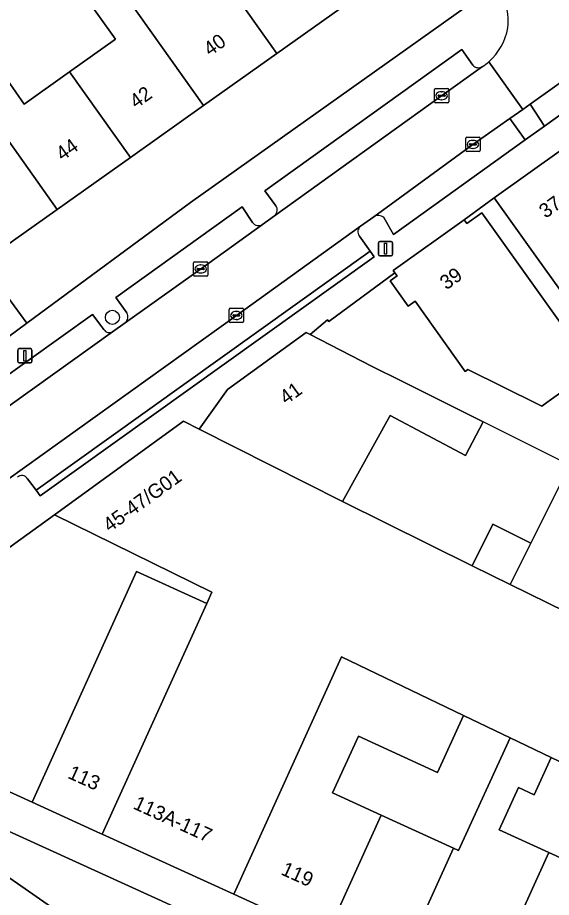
# Model space of a CAD drawing. Extents: x 161881 to 162523, y 381678 to 382381.
# Drawn here: x 162188.6 to 162225.8, y 381835.8 to 381897.2 of the extents above; entities that cross this region are included whole.
import ezdxf

# ---------------------------------------------------------------- set-up
doc = ezdxf.new("R2010")
doc.units = 0
for name, color, linetype in [('IMGEO_Boom', 7, 'Continuous'), ('IMGEO_Erf', 7, 'Continuous'), ('IMGEO_Fietspad_open', 7, 'Continuous'), ('IMGEO_Groenvoorziening', 7, 'Continuous'), ('IMGEO_Kolk', 7, 'Continuous'), ('IMGEO_Lichtmast', 7, 'Continuous'), ('IMGEO_Muur', 7, 'Continuous'), ('IMGEO_Pand', 7, 'Continuous'), ('IMGEO_Pand_nummerreeks', 7, 'Continuous'), ('IMGEO_Parkeervlak_open', 7, 'Continuous'), ('IMGEO_Rijbaan_lokaal_gesloten', 7, 'Continuous'), ('IMGEO_Rijbaan_lokaal_open', 7, 'Continuous'), ('IMGEO_Voetpad_open', 7, 'Continuous')]:
    doc.layers.add(name, color=color, linetype=linetype)

msp = doc.modelspace()

# ---------------------------------------------------------------- linework, layer by layer
at = {"layer": 'IMGEO_Boom'}
msp.add_circle((162195.219, 381876.245), 0.489, dxfattribs=at)
at = {"layer": 'IMGEO_Erf'}
for points in [[(162192.985, 381899.113), (162194.885, 381900.463), (162197.327, 381902.197), (162199.786, 381898.734), (162202.449, 381900.625), (162205.043, 381902.467), (162199.857, 381909.77), (162197.982, 381912.41), (162174.798, 381896.036), (162181.899, 381886.04), (162184.511, 381887.894), (162183.222, 381889.708), (162183.269, 381891.068), (162182.383, 381892.316), (162180.235, 381895.341), (162182.182, 381896.724), (162184.329, 381893.698), (162186.276, 381895.081), (162187.902, 381892.79), (162189.079, 381891.131), (162192.238, 381893.374), (162195.444, 381895.65)], [(162219.928, 381897.942), (162217.025, 381901.99), (162216.426, 381901.565), (162216.676, 381900.636), (162214.964, 381899.393), (162214.161, 381899.956), (162211.795, 381898.276), (162206.689, 381894.65), (162201.583, 381891.024), (162196.478, 381887.399), (162191.372, 381883.773), (162186.145, 381880.061), (162189.26, 381875.839), (162200.679, 381884.262)], [(162217.888, 381844.488), (162212.383, 381847.004), (162210.577, 381843.05), (162213.957, 381841.506), (162219.021, 381839.193), (162219.368, 381839.034), (162222.963, 381846.903), (162219.706, 381848.467)], [(162237.733, 381842.257), (162241.739, 381840.426), (162242.567, 381842.238), (162238.73, 381843.992), (162238.196, 381842.822), (162232.406, 381845.468), (162230.931, 381843.076), (162225.821, 381845.53), (162224.634, 381842.932), (162223.557, 381843.424), (162222.21, 381840.476), (162225.66, 381838.899), (162230.754, 381836.572), (162229.277, 381833.339), (162225.862, 381825.851), (162227.18, 381825.249), (162228.266, 381824.753), (162228.546, 381824.625), (162231.967, 381832.11), (162233.525, 381835.519), (162234.459, 381835.092)]]:
    msp.add_lwpolyline(points, close=True, dxfattribs=at)
msp.add_lwpolyline([(162227.003, 381877.365), (162224.754, 381880.517), (162221.85, 381884.587), (162219.757, 381883.039), (162219.932, 381882.795), (162220.983, 381883.545), (162228.778, 381872.621), (162225.523, 381870.299), (162225.177, 381870.052), (162225.045, 381870.118), (162224.95, 381870.164), (162220.024, 381872.598), (162219.836, 381872.464), (162216.329, 381877.377), (162215.841, 381877.029), (162214.585, 381878.789), (162215.074, 381879.138), (162214.928, 381879.343), (162210.308, 381875.962), (162210.218, 381876.081), (162209.012, 381875.04), (162213.292, 381872.838), (162215.453, 381871.759), (162221.091, 381868.944), (162219.842, 381866.613), (162214.594, 381869.388), (162211.275, 381863.392), (162220.321, 381858.911), (162221.768, 381861.808), (162224.418, 381860.495), (162227.131, 381865.927)], dxfattribs=at)
at = {"layer": 'IMGEO_Fietspad_open'}
for points in [[(162297.281, 381790.934), (162283.991, 381796.906), (162276.913, 381800.086), (162237.824, 381817.651), (162177.947, 381844.935)], [(162183.799, 381840.053), (162184.069, 381839.866), (162192.812, 381833.805), (162194.089, 381833.367), (162198.754, 381831.251), (162197.694, 381828.855), (162197.222, 381827.799), (162199.963, 381826.58), (162201.558, 381830.008), (162248.9, 381808.653), (162250.093, 381808.023), (162257.97, 381806.387), (162264.876, 381803.292), (162275.916, 381798.35), (162283.117, 381795.079), (162296.058, 381789.157)]]:
    msp.add_lwpolyline(points, dxfattribs=at)
at = {"layer": 'IMGEO_Groenvoorziening'}
msp.add_lwpolyline([(162225.354, 381889.595), (162224.359, 381891.116), (162223.84, 381890.752), (162222.952, 381890.129), (162224.004, 381888.624)], close=True, dxfattribs=at)
at = {"layer": 'IMGEO_Kolk'}
for p, q in [((162217.682, 381891.288), (162217.682, 381892.14)), ((162217.757, 381892.214), (162218.609, 381892.214)), ((162218.17, 381891.994), (162218.195, 381891.994)), ((162218.683, 381892.14), (162218.683, 381891.288)), ((162217.941, 381891.708), (162217.941, 381891.72)), ((162218.379, 381891.671), (162217.981, 381891.671)), ((162217.984, 381891.757), (162218.382, 381891.757)), ((162218.193, 381891.434), (162218.168, 381891.434)), ((162218.425, 381891.72), (162218.425, 381891.708)), ((162218.609, 381891.214), (162217.757, 381891.214)), ((162219.943, 381888.815), (162220.795, 381888.815)), ((162219.868, 381887.889), (162219.868, 381888.741)), ((162220.127, 381888.309), (162220.127, 381888.321)), ((162220.565, 381888.272), (162220.167, 381888.272)), ((162220.17, 381888.358), (162220.568, 381888.358)), ((162220.356, 381888.595), (162220.381, 381888.595)), ((162220.611, 381888.321), (162220.611, 381888.309)), ((162220.869, 381888.741), (162220.869, 381887.889)), ((162220.795, 381887.815), (162219.943, 381887.815)), ((162220.379, 381888.035), (162220.354, 381888.035)), ((162200.88, 381879.193), (162200.88, 381880.045)), ((162200.955, 381880.119), (162201.807, 381880.119)), ((162201.139, 381879.613), (162201.139, 381879.625)), ((162201.577, 381879.576), (162201.179, 381879.576)), ((162201.182, 381879.662), (162201.58, 381879.662)), ((162201.368, 381879.899), (162201.393, 381879.899)), ((162201.623, 381879.625), (162201.623, 381879.613)), ((162201.881, 381880.045), (162201.881, 381879.193)), ((162201.807, 381879.119), (162200.955, 381879.119)), ((162201.391, 381879.339), (162201.366, 381879.339)), ((162203.369, 381875.95), (162203.369, 381876.802)), ((162203.444, 381876.876), (162204.296, 381876.876)), ((162203.857, 381876.656), (162203.882, 381876.656)), ((162204.37, 381876.802), (162204.37, 381875.95)), ((162204.296, 381875.876), (162203.444, 381875.876)), ((162203.628, 381876.37), (162203.628, 381876.382)), ((162204.066, 381876.333), (162203.668, 381876.333)), ((162203.671, 381876.419), (162204.069, 381876.419)), ((162203.88, 381876.096), (162203.855, 381876.096)), ((162204.112, 381876.382), (162204.112, 381876.37))]:
    msp.add_line(p, q, dxfattribs=at)
for points in [[(162217.682, 381891.288), (162217.682, 381892.14)], [(162217.757, 381892.214), (162218.609, 381892.214)], [(162218.683, 381892.14), (162218.683, 381891.288)], [(162218.609, 381891.214), (162217.757, 381891.214)], [(162219.943, 381888.815), (162220.795, 381888.815)], [(162219.868, 381887.889), (162219.868, 381888.741)], [(162220.869, 381888.741), (162220.869, 381887.889)], [(162220.795, 381887.815), (162219.943, 381887.815)], [(162200.88, 381879.193), (162200.88, 381880.045)], [(162200.955, 381880.119), (162201.807, 381880.119)], [(162201.881, 381880.045), (162201.881, 381879.193)], [(162201.807, 381879.119), (162200.955, 381879.119)], [(162203.369, 381875.95), (162203.369, 381876.802)], [(162203.444, 381876.876), (162204.296, 381876.876)], [(162204.37, 381876.802), (162204.37, 381875.95)], [(162204.296, 381875.876), (162203.444, 381875.876)]]:
    msp.add_lwpolyline(points, dxfattribs=at)
for centre, radius, start, end in [((162217.759, 381892.138), 0.0765, 91.55205, 178.44795), ((162217.759, 381892.138), 0.0765, 91.55205, 178.44795), ((162218.607, 381892.138), 0.0765, 1.55205, 88.44795), ((162218.607, 381892.138), 0.0765, 1.55205, 88.44795), ((162217.759, 381891.29), 0.0765, 181.55205, 268.44795), ((162217.759, 381891.29), 0.0765, 181.55205, 268.44795), ((162217.981, 381891.717), 0.0403, 85.87752, 175.75265), ((162217.978, 381891.707), 0.0366, 178.93798, 274.71019), ((162218.382, 381891.714), 0.043, 264.86636, 352.45326), ((162218.386, 381891.719), 0.0386, 1.73085, 96.63898), ((162218.607, 381891.29), 0.0765, 271.55205, 358.44795), ((162218.607, 381891.29), 0.0765, 271.55205, 358.44795), ((162219.945, 381888.739), 0.0765, 91.55205, 178.44795), ((162219.945, 381888.739), 0.0765, 91.55205, 178.44795), ((162220.793, 381888.739), 0.0765, 1.55205, 88.44795), ((162220.793, 381888.739), 0.0765, 1.55205, 88.44795), ((162220.167, 381888.318), 0.0403, 85.87752, 175.75265), ((162220.164, 381888.308), 0.0366, 178.93798, 274.71019), ((162220.568, 381888.315), 0.043, 264.86636, 352.45326), ((162220.572, 381888.32), 0.0386, 1.73085, 96.63898), ((162219.945, 381887.891), 0.0765, 181.55205, 268.44795), ((162219.945, 381887.891), 0.0765, 181.55205, 268.44795), ((162220.793, 381887.891), 0.0765, 271.55205, 358.44795), ((162220.793, 381887.891), 0.0765, 271.55205, 358.44795), ((162200.957, 381880.043), 0.0765, 91.55205, 178.44795), ((162200.957, 381880.043), 0.0765, 91.55205, 178.44795), ((162201.179, 381879.622), 0.0403, 85.87752, 175.75265), ((162201.176, 381879.612), 0.0366, 178.93798, 274.71019), ((162201.58, 381879.619), 0.043, 264.86636, 352.45326), ((162201.584, 381879.624), 0.0386, 1.73085, 96.63898), ((162201.805, 381880.043), 0.0765, 1.55205, 88.44795), ((162201.805, 381880.043), 0.0765, 1.55205, 88.44795), ((162200.957, 381879.195), 0.0765, 181.55205, 268.44795), ((162200.957, 381879.195), 0.0765, 181.55205, 268.44795), ((162201.805, 381879.195), 0.0765, 271.55205, 358.44795), ((162201.805, 381879.195), 0.0765, 271.55205, 358.44795), ((162203.446, 381876.8), 0.0765, 91.55205, 178.44795), ((162203.446, 381876.8), 0.0765, 91.55205, 178.44795), ((162204.294, 381876.8), 0.0765, 1.55205, 88.44795), ((162204.294, 381876.8), 0.0765, 1.55205, 88.44795), ((162203.446, 381875.952), 0.0765, 181.55205, 268.44795), ((162203.446, 381875.952), 0.0765, 181.55205, 268.44795), ((162203.668, 381876.379), 0.0403, 85.87752, 175.75265), ((162203.665, 381876.369), 0.0366, 178.93798, 274.71019), ((162204.069, 381876.376), 0.043, 264.86636, 352.45326), ((162204.073, 381876.381), 0.0386, 1.73085, 96.63898), ((162204.294, 381875.952), 0.0765, 271.55205, 358.44795), ((162204.294, 381875.952), 0.0765, 271.55205, 358.44795)]:
    msp.add_arc(centre, radius, start, end, dxfattribs=at)
for centre, major_axis, ratio, start_param, end_param in [((162218.169, 381891.714), (-0.387, 0.002), 0.722429, 4.712389, 7.853982), ((162218.194, 381891.714), (-0.39, 0.002), 0.717154, 1.570796, 4.712389), ((162220.355, 381888.315), (-0.387, 0.002), 0.722429, 4.712389, 7.853982), ((162220.38, 381888.315), (-0.39, 0.002), 0.717154, 1.570796, 4.712389), ((162201.367, 381879.619), (-0.387, 0.002), 0.722429, 4.712389, 7.853982), ((162201.392, 381879.619), (-0.39, 0.002), 0.717154, 1.570796, 4.712389), ((162203.856, 381876.376), (-0.387, 0.002), 0.722429, 4.712389, 7.853982), ((162203.881, 381876.376), (-0.39, 0.002), 0.717154, 1.570796, 4.712389)]:
    msp.add_ellipse(centre, major_axis=major_axis, ratio=ratio, start_param=start_param, end_param=end_param, dxfattribs=at)
at = {"layer": 'IMGEO_Lichtmast'}
for p, q in [((162213.773, 381880.636), (162213.773, 381881.436)), ((162213.773, 381881.436), (162213.773, 381880.636)), ((162213.873, 381881.536), (162214.663, 381881.536)), ((162214.663, 381881.536), (162213.873, 381881.536)), ((162214.763, 381881.436), (162214.763, 381880.636)), ((162214.763, 381880.636), (162214.763, 381881.436)), ((162214.663, 381880.536), (162213.873, 381880.536)), ((162213.873, 381880.536), (162214.663, 381880.536)), ((162188.721, 381874.06), (162189.511, 381874.06)), ((162189.511, 381874.06), (162188.721, 381874.06)), ((162188.621, 381873.16), (162188.621, 381873.96)), ((162188.621, 381873.96), (162188.621, 381873.16)), ((162189.611, 381873.96), (162189.611, 381873.16)), ((162189.611, 381873.16), (162189.611, 381873.96)), ((162189.511, 381873.06), (162188.721, 381873.06)), ((162188.721, 381873.06), (162189.511, 381873.06))]:
    msp.add_line(p, q, dxfattribs=at)
for points in [[(162214.193, 381881.411), (162214.343, 381881.411), (162214.343, 381880.661), (162214.193, 381880.661), (162214.193, 381881.411)], [(162189.041, 381873.935), (162189.191, 381873.935), (162189.191, 381873.185), (162189.041, 381873.185), (162189.041, 381873.935)]]:
    msp.add_lwpolyline(points, dxfattribs=at)
for centre, start, end in [((162213.873, 381881.436), 90, 180), ((162213.873, 381881.436), 90, 180), ((162214.663, 381881.436), 0, 90), ((162214.663, 381881.436), 360, 90), ((162213.873, 381880.636), 180, 270), ((162213.873, 381880.636), 180, 270), ((162214.663, 381880.636), 270, 0), ((162214.663, 381880.636), 270, 0), ((162188.721, 381873.96), 90, 180), ((162188.721, 381873.96), 90, 180), ((162189.511, 381873.96), 0, 90), ((162189.511, 381873.96), 360, 90), ((162188.721, 381873.16), 180, 270), ((162188.721, 381873.16), 180, 270), ((162189.511, 381873.16), 270, 0), ((162189.511, 381873.16), 270, 0)]:
    msp.add_arc(centre, 0.1, start, end, dxfattribs=at)
at = {"layer": 'IMGEO_Muur'}
msp.add_lwpolyline([(162227.131, 381865.927), (162221.091, 381868.944)], dxfattribs=at)
at = {"layer": 'IMGEO_Pand'}
for points in [[(162204.956, 381907.913), (162204.692, 381908.284), (162202.369, 381911.555), (162202.23, 381911.749), (162200.492, 381914.183), (162197.982, 381912.41), (162199.857, 381909.77), (162205.043, 381902.467), (162202.449, 381900.625), (162206.689, 381894.65), (162211.795, 381898.276)], [(162201.583, 381891.024), (162206.689, 381894.65), (162202.449, 381900.625), (162199.786, 381898.734), (162197.327, 381902.197), (162194.885, 381900.463)], [(162192.238, 381893.374), (162196.478, 381887.399), (162201.583, 381891.024), (162194.885, 381900.463), (162192.985, 381899.113), (162195.444, 381895.65)], [(162192.238, 381893.374), (162189.079, 381891.131), (162187.902, 381892.79), (162186.276, 381895.081), (162184.329, 381893.698), (162191.372, 381883.773), (162196.478, 381887.399)], [(162184.329, 381893.698), (162182.383, 381892.316), (162183.269, 381891.068), (162183.222, 381889.708), (162184.511, 381887.894), (162181.899, 381886.04), (162183.25, 381884.138), (162186.145, 381880.061), (162191.372, 381883.773)], [(162226.702, 381888.049), (162221.85, 381884.587), (162224.754, 381880.517), (162227.003, 381877.365), (162229.505, 381879.151), (162232.792, 381874.544), (162233.959, 381872.909), (162235.876, 381874.277), (162236.307, 381873.673), (162236.344, 381873.289), (162236.869, 381873.804)], [(162220.983, 381883.545), (162219.932, 381882.795), (162219.757, 381883.039), (162214.81, 381879.508), (162214.928, 381879.343), (162215.074, 381879.138), (162214.585, 381878.789), (162215.841, 381877.029), (162216.329, 381877.377), (162219.836, 381872.464), (162220.024, 381872.598), (162224.95, 381870.164), (162225.045, 381870.118), (162225.177, 381870.052), (162225.523, 381870.299), (162228.778, 381872.621)], [(162215.453, 381871.759), (162213.292, 381872.838), (162209.012, 381875.04), (162208.741, 381875.18), (162203.258, 381871.214), (162201.278, 381868.442), (162211.275, 381863.392), (162214.594, 381869.388), (162219.842, 381866.613), (162221.091, 381868.944)], [(162222.972, 381857.598), (162220.321, 381858.911), (162211.275, 381863.392), (162201.278, 381868.442), (162200.189, 381868.993), (162191.173, 381862.471), (162202.159, 381857.074), (162201.802, 381856.284), (162194.508, 381840.175), (162203.692, 381835.979), (162211.21, 381852.547), (162219.706, 381848.467), (162222.963, 381846.903), (162225.821, 381845.53), (162230.931, 381843.076), (162232.406, 381845.468), (162235.949, 381851.214)], [(162228.776, 381865.106), (162227.131, 381865.927), (162224.418, 381860.495), (162222.972, 381857.598), (162235.949, 381851.214), (162240.666, 381858.867)], [(162196.913, 381858.497), (162201.802, 381856.284), (162202.159, 381857.074), (162191.173, 381862.471), (162180.837, 381854.994), (162178.376, 381849.609), (162179.207, 381847.165), (162189.628, 381842.404)], [(162224.418, 381860.495), (162221.768, 381861.808), (162220.321, 381858.911), (162222.972, 381857.598)], [(162189.628, 381842.404), (162194.384, 381840.231), (162194.508, 381840.175), (162201.802, 381856.284), (162196.913, 381858.497)], [(162213.957, 381841.506), (162210.577, 381843.05), (162212.383, 381847.004), (162217.888, 381844.488), (162219.706, 381848.467), (162211.21, 381852.547), (162203.692, 381835.979), (162210.124, 381833.041)], [(162220.8, 381828.163), (162225.66, 381838.899), (162222.21, 381840.476), (162223.557, 381843.424), (162224.634, 381842.932), (162225.821, 381845.53), (162222.963, 381846.903), (162219.368, 381839.034), (162219.021, 381839.193), (162215.188, 381830.727)], [(162219.021, 381839.193), (162213.957, 381841.506), (162210.124, 381833.041), (162215.188, 381830.727)], [(162229.277, 381833.339), (162230.754, 381836.572), (162225.66, 381838.899), (162220.8, 381828.163), (162225.862, 381825.851)]]:
    msp.add_lwpolyline(points, close=True, dxfattribs=at)
at = {"layer": 'IMGEO_Parkeervlak_open'}
for points in [[(162273.463, 381926.395), (162269.991, 381923.887), (162260.256, 381916.887), (162257.825, 381915.139), (162253.349, 381911.92), (162238.365, 381901.138), (162234.555, 381898.412), (162224.359, 381891.116), (162225.354, 381889.595), (162274.088, 381924.659), (162273.358, 381925.677)], [(162220.354, 381893.843), (162219.602, 381894.939), (162205.852, 381885.082), (162206.624, 381884.037)], [(162206.52, 381883.338), (162218.181, 381891.71), (162221.037, 381893.752)], [(162214.15, 381883.202), (162214.822, 381882.018), (162224.004, 381888.624), (162222.952, 381890.129), (162220.372, 381888.318), (162213.447, 381883.269)], [(162204.993, 381882.873), (162204.28, 381883.952), (162195.47, 381877.637), (162196.233, 381876.562)], [(162196.109, 381875.864), (162201.378, 381879.615), (162205.695, 381882.731)], [(162212.528, 381882.597), (162203.872, 381876.38), (162180.448, 381859.581)], [(162189.297, 381864.98), (162189.895, 381864.185), (162213.199, 381880.867), (162212.451, 381881.917)], [(162194.635, 381875.39), (162193.827, 381876.453), (162180.57, 381866.951), (162181.366, 381865.831)], [(162181.253, 381865.225), (162195.238, 381875.244)]]:
    msp.add_lwpolyline(points, dxfattribs=at)
for centre, radius, start, end in [((162220.748, 381894.191), 0.526, 221.48306, 303.33864), ((162206.22, 381883.74), 0.502, 306.74932, 36.32546), ((162213.754, 381882.774), 0.583, 47.28945, 121.8222), ((162205.413, 381883.141), 0.498, 212.56947, 304.55964), ((162212.811, 381882.221), 0.471, 126.90579, 220.17344), ((162195.719, 381876.293), 0.58, 312.27748, 27.57547), ((162195.008, 381875.612), 0.434, 210.72343, 302.05522), ((162188.912, 381864.775), 0.436, 27.98029, 135.69046)]:
    msp.add_arc(centre, radius, start, end, dxfattribs=at)
at = {"layer": 'IMGEO_Rijbaan_lokaal_gesloten'}
msp.add_lwpolyline([(162184.849, 381834.538), (162188.858, 381834.274), (162189.051, 381834.251), (162192.812, 381833.805), (162184.069, 381839.866)], dxfattribs=at)
at = {"layer": 'IMGEO_Rijbaan_lokaal_open'}
for points in [[(162221.475, 381894.082), (162223.84, 381890.752), (162224.359, 381891.116), (162234.555, 381898.412)], [(162221.037, 381893.752), (162218.181, 381891.71), (162206.52, 381883.338), (162205.695, 381882.731), (162201.378, 381879.615), (162196.109, 381875.864), (162195.238, 381875.244), (162181.253, 381865.225), (162181.154, 381865.154), (162177.47, 381862.483), (162175.076, 381860.748), (162174.221, 381860.14), (162173.371, 381859.537), (162172.481, 381858.791), (162169.555, 381856.117), (162167.602, 381854.382), (162171.848, 381851.823), (162172.135, 381852.084), (162172.323, 381852.389)], [(162180.448, 381859.581), (162203.872, 381876.38), (162212.528, 381882.597), (162213.447, 381883.269), (162220.372, 381888.318), (162222.952, 381890.129), (162223.84, 381890.752), (162221.475, 381894.082)]]:
    msp.add_lwpolyline(points, dxfattribs=at)
for centre, radius, start, end in [((162218.505, 381896.928), 4.318, 353.65476, 18.04766), ((162218.85, 381897.1), 4, 311.01175, 350.6616), ((162218.8, 381897.176), 4.09, 303.15137, 310.83917)]:
    msp.add_arc(centre, radius, start, end, dxfattribs=at)
at = {"layer": 'IMGEO_Voetpad_open'}
for points in [[(162273.358, 381925.677), (162274.088, 381924.659), (162225.354, 381889.595), (162224.004, 381888.624), (162214.822, 381882.018), (162214.15, 381883.202)], [(162169.12, 381899.743), (162171.643, 381897.136), (162172.317, 381896.44), (162179.758, 381886.011), (162187.895, 381874.832), (162189.26, 381875.839), (162186.145, 381880.061), (162183.25, 381884.138), (162181.899, 381886.04), (162174.798, 381896.036), (162197.982, 381912.41)], [(162222.611, 381898.266), (162222.089, 381899.341), (162219.928, 381897.942), (162200.679, 381884.262), (162189.26, 381875.839), (162187.895, 381874.832), (162187.997, 381874.692), (162184.9, 381872.437), (162184.296, 381873.278), (162182.635, 381872.084), (162180.973, 381870.888), (162181.45, 381870.226), (162178.278, 381867.945), (162176.595, 381866.681), (162173.176, 381864.352), (162172.99, 381864.214), (162170.693, 381862.513), (162162.832, 381856.692), (162167.236, 381854.058), (162167.602, 381854.382), (162169.555, 381856.117)], [(162206.624, 381884.037), (162205.852, 381885.082), (162219.602, 381894.939), (162220.354, 381893.843)], [(162172.135, 381852.084), (162171.848, 381851.823), (162171.631, 381851.44), (162177.609, 381847.871), (162179.207, 381847.165), (162178.376, 381849.609), (162180.837, 381854.994), (162191.173, 381862.471), (162200.189, 381868.993), (162201.278, 381868.442), (162203.258, 381871.214), (162208.741, 381875.18), (162209.012, 381875.04), (162210.218, 381876.081), (162210.308, 381875.962), (162214.928, 381879.343), (162214.81, 381879.508), (162219.757, 381883.039), (162221.85, 381884.587), (162226.702, 381888.049)], [(162196.233, 381876.562), (162195.47, 381877.637), (162204.28, 381883.952), (162204.993, 381882.873)], [(162205.695, 381882.731), (162206.52, 381883.338)], [(162213.447, 381883.269), (162212.528, 381882.597)], [(162212.451, 381881.917), (162213.199, 381880.867), (162213.49, 381880.461), (162190.186, 381863.779), (162189.895, 381864.185), (162189.297, 381864.98)], [(162181.366, 381865.831), (162180.57, 381866.951), (162193.827, 381876.453), (162194.635, 381875.39)], [(162195.238, 381875.244), (162196.109, 381875.864)], [(162203.692, 381835.979), (162194.508, 381840.175), (162194.384, 381840.231), (162189.628, 381842.404), (162179.207, 381847.165), (162177.609, 381847.871), (162171.631, 381851.44), (162171.296, 381850.551)], [(162177.947, 381844.935), (162237.824, 381817.651), (162276.913, 381800.086), (162283.991, 381796.906), (162297.281, 381790.934)], [(162225.862, 381825.851), (162220.8, 381828.163), (162215.188, 381830.727), (162210.124, 381833.041), (162203.692, 381835.979)]]:
    msp.add_lwpolyline(points, dxfattribs=at)
msp.add_lwpolyline([(162213.199, 381880.867), (162189.895, 381864.185), (162190.186, 381863.779), (162213.49, 381880.461)], close=True, dxfattribs=at)
for centre, radius, start, end in [((162218.505, 381896.928), 4.318, 353.65476, 18.04766), ((162218.85, 381897.1), 4, 311.01175, 350.6616), ((162220.748, 381894.191), 0.526, 221.48306, 303.33864), ((162218.8, 381897.176), 4.09, 303.15137, 310.83917), ((162206.22, 381883.74), 0.502, 306.74932, 36.32546), ((162213.754, 381882.774), 0.583, 47.28945, 121.8222), ((162205.413, 381883.141), 0.498, 212.56947, 304.55964), ((162212.811, 381882.221), 0.471, 126.90579, 220.17344), ((162195.719, 381876.293), 0.58, 312.27748, 27.57547), ((162195.008, 381875.612), 0.434, 210.72343, 302.05522), ((162188.912, 381864.775), 0.436, 27.98029, 135.69046)]:
    msp.add_arc(centre, radius, start, end, dxfattribs=at)

# ---------------------------------------------------------------- texts
at = {"layer": 'IMGEO_Pand_nummerreeks'}
for s, rotation, p in [('40', 35.37993, (162202.028, 381894.431)), ('42', 35.37993, (162196.877, 381890.773)), ('44', 35.38014, (162191.732, 381887.12)), ('37', 35.50619, (162225.434, 381883.114)), ('39', 35.51765, (162218.516, 381878.123)), ('41', 35.87862, (162207.344, 381870.12)), ('45-47/G01', 35.87862, (162195.028, 381861.211)), ('113', 335.64177, (162192.038, 381844.121)), ('113A-117', 335.36281, (162196.602, 381841.986)), ('119', 335.64551, (162206.911, 381837.387))]:
    msp.add_text(s, height=1, rotation=rotation, dxfattribs=at).set_placement(p)

doc.saveas('drawing.dxf')
